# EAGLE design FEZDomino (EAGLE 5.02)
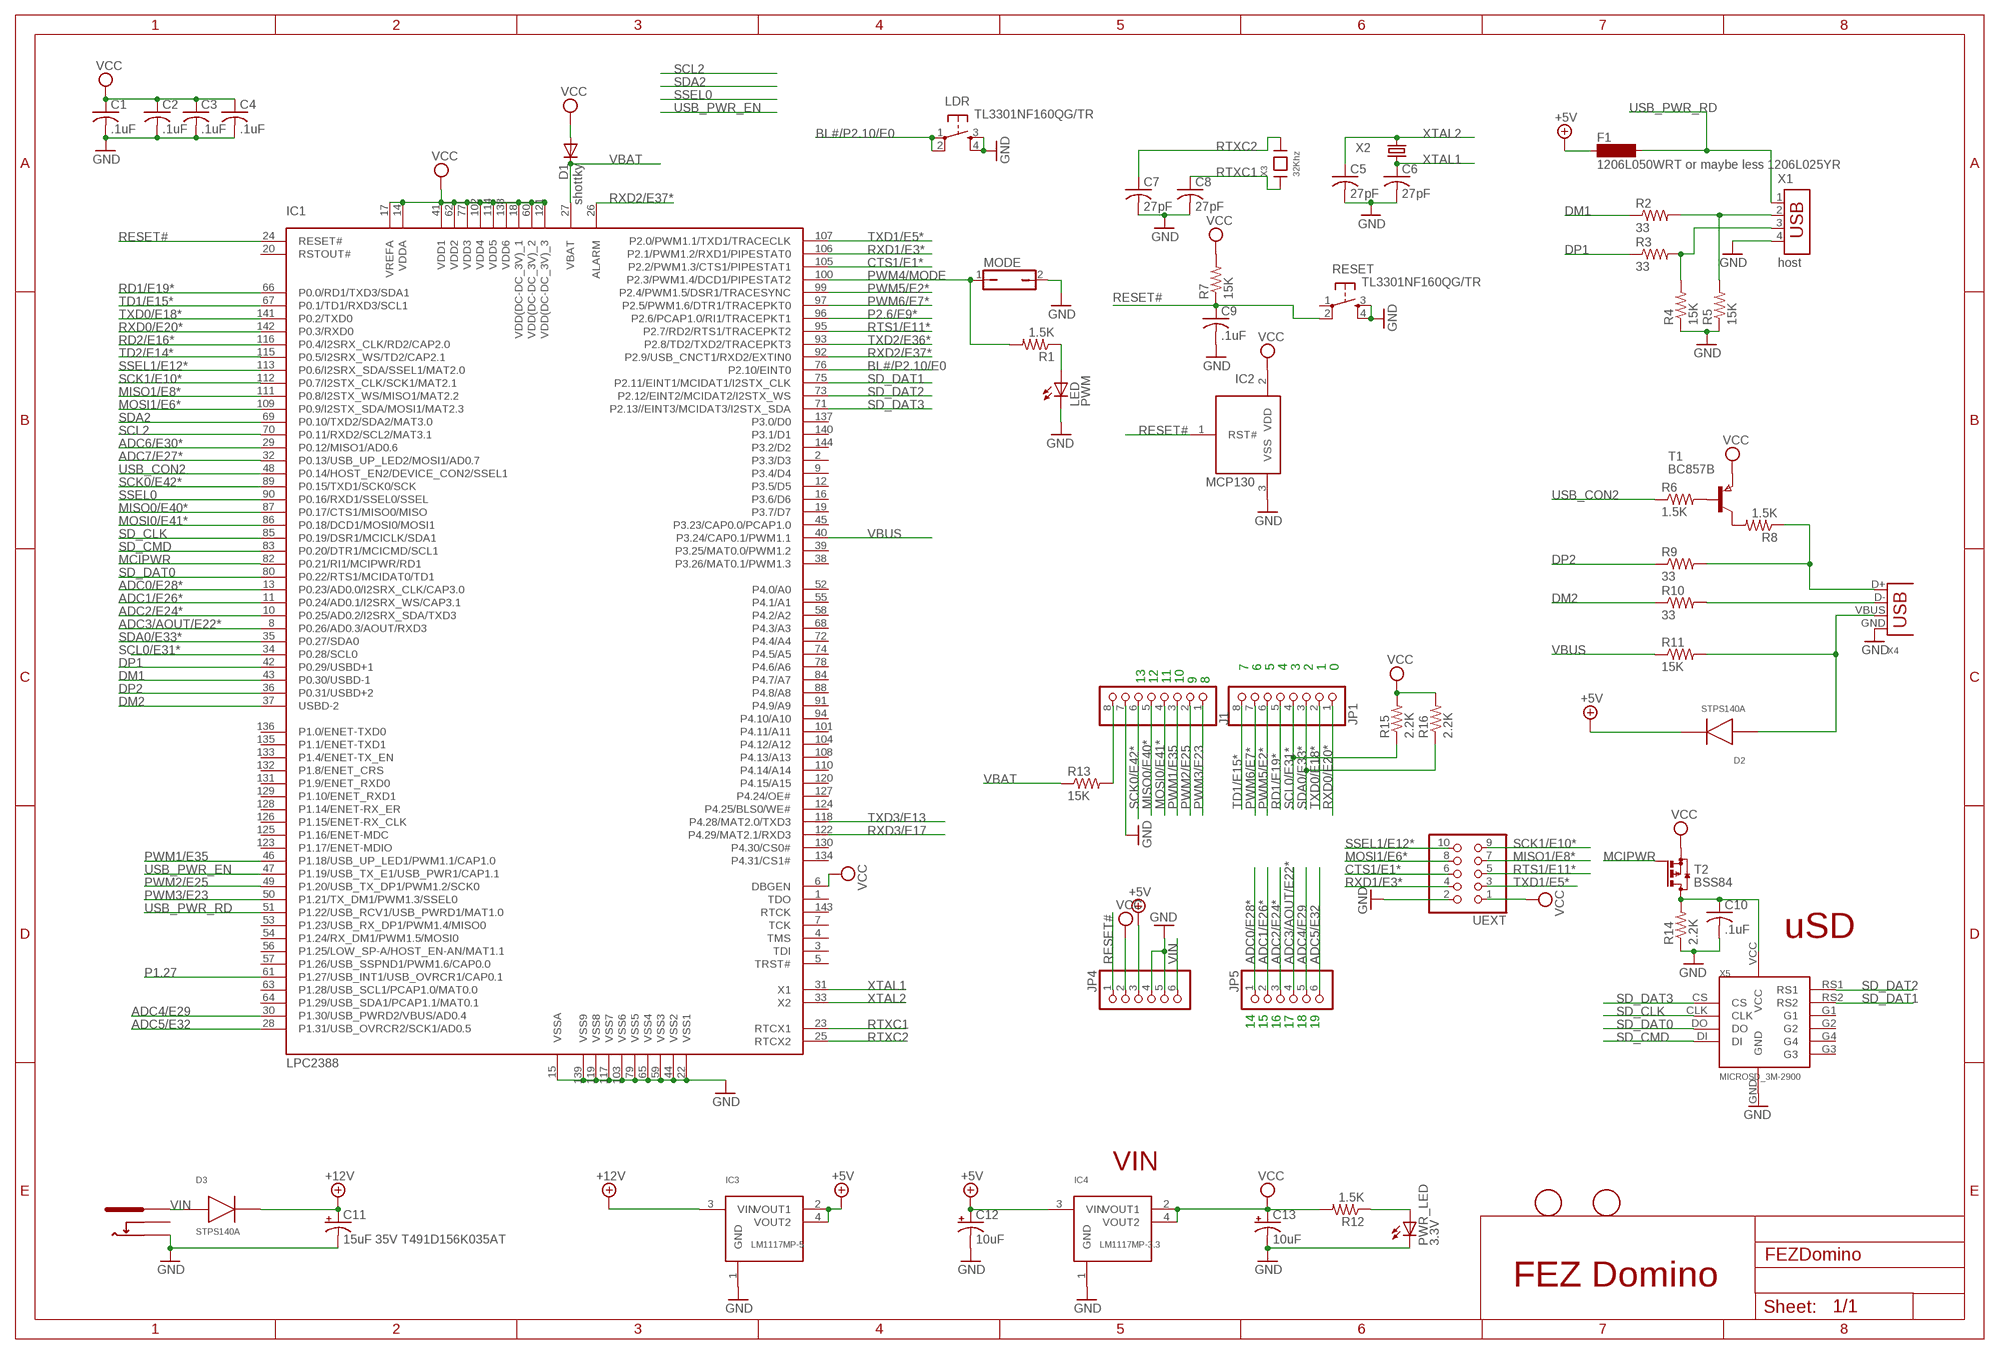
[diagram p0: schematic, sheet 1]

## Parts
C1  .1uF  C-USC0603K  [C0603K]
C2  .1uF  C-USC0603K  [C0603K]
C3  .1uF  C-USC0603K  [C0603K]
C4  .1uF  C-USC0603K  [C0603K]
C5  27pF  C-USC0603K  [C0603K]
C6  27pF  C-USC0603K  [C0603K]
C7  27pF  C-USC0603K  [C0603K]
C8  27pF  C-USC0603K  [C0603K]
C9  .1uF  C-USC0603K  [C0603K]
C10  .1uF  C-USC0603  [C0603]
C11  15uF 35V T491D156K035AT  CPOL-USD/7343-31W  [D/7343-31W]
C12  10uF  CPOL-USCT3528  [CT3528]
C13  10uF  CPOL-USCT3528  [CT3528]
D1  shottky  DIODE-SOD323-W  [SOD323-W]
D2  STPS140A  DIODE_SMA  [DIODE_SMA]
D3  STPS140A  DIODE_SMA  [DIODE_SMA]
F1  1206L050WRT or maybe less 1206L025YR  SM-1206  [SM-1206]
IC1  LPC2388  [LQFP144]
IC2  MCP130  [SOT23]
IC3  LM1117MP-5  LM1117  [SOT223]
IC4  LM1117MP-3.3  LM1117  [SOT223]
J1  PINHD-1X8  [1X08]
JP1  PINHD-1X8  [1X08]
JP4  PINHD-1X6  [1X06]
JP5  PINHD-1X6  [1X06]
LDR  TL3301NF160QG/TR  DTSM-6  [DTSM-6]
LED  PWM  LEDCHIPLED_0805  [CHIPLED_0805]
MODE  JP1Q  [JP1]
PWR_LED  3.3V  LEDCHIPLED_0805  [CHIPLED_0805]
R1  1.5K  R-US_R0603  [R0603]
R2  33  R-US_R0603  [R0603]
R3  33  R-US_R0603  [R0603]
R4  15K  R-US_R0603  [R0603]
R5  15K  R-US_R0603  [R0603]
R6  1.5K  R-US_R0603  [R0603]
R7  15K  R-US_R0603  [R0603]
R8  1.5K  R-US_R0603  [R0603]
R9  33  R-US_R0603  [R0603]
R10  33  R-US_R0603  [R0603]
R11  15K  R-US_R0603  [R0603]
R12  1.5K  R-US_R0603  [R0603]
R13  15K  R-US_R0603  [R0603]
R14  2.2K  R-US_R0603  [R0603]
R15  2.2K  R-US_R0603  [R0603]
R16  2.2K  R-US_R0603  [R0603]
RESET  TL3301NF160QG/TR  DTSM-6  [DTSM-6]
T1  BC857B  PNPSOT23  [SOT-23]
T2  BSS84  [SOT23]
U$1  FIDUCIALMOUNT  [FIDUCIA-MOUNT]
U$2  FIDUCIALMOUNT  [FIDUCIA-MOUNT]
UEXT  PINHD-2X5  [2X05]
X1  host  USB-787616  [USB]
X2  12Mhz  CRYTALSM49  [SM49]
X3  32Khz  CRYSTAL_6.9X1.4  [CRYSTAL_6.9X1.4]
X4  DX2R005HN2E700  USB-MB-S  [USB-MB-S]
X5  MICROSD_3M-2900  [USD_3M-2900]
X6  PJ-102B_POWER_CON  [PJ-102B_POWER_CON]

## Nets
+5V: C12.+ D2.K F1.1 IC3.2(VOUT1) IC3.4(VOUT2) IC4.3(VIN) JP4.3
+12V: C11.+ D3.K IC3.3(VIN)
ADC0/E28*: IC1.13(P0.23/AD0.0/I2SRX_CLK/CAP3.0) JP5.1
ADC1/E26*: IC1.11(P0.24/AD0.1/I2SRX_WS/CAP3.1) JP5.2
ADC2/E24*: IC1.10(P0.25/AD0.2/I2SRX_SDA/TXD3) JP5.3
ADC3/AOUT/E22*: IC1.8(P0.26/AD0.3/AOUT/RXD3) JP5.4
ADC4/E29: IC1.30(P1.30/USB_PWRD2/VBUS/AD0.4) JP5.5
ADC5/E32: IC1.28(P1.31/USB_OVRCR2/SCK1/AD0.5) JP5.6
ADC6/E30*: IC1.29(P0.12/MISO1/AD0.6)
ADC7/E27*: IC1.32(P0.13/USB_UP_LED2/MOSI1/AD0.7)
BL#/P2.10/E0: IC1.76(P2.10/EINT0) LDR.1 LDR.2
CTS1/E1*: IC1.105(P2.2/PWM1.3/CTS1/PIPESTAT1) UEXT.6
DM1: IC1.43(P0.30/USBD-1) R2.1
DM2: IC1.37(USBD-2) R10.1
DP1: IC1.42(P0.29/USBD+1) R3.1
DP2: IC1.36(P0.31/USBD+2) R9.1
GND: C1.2 C2.2 C3.2 C4.2 C5.2 C6.2 C7.2 C8.2 C9.2 C10.2 C11.- C12.- C13.- IC1.15(VSSA) IC1.22(VSS1) IC1.44(VSS2) IC1.59(VSS3) IC1.65(VSS4) IC1.79(VSS5) IC1.103(VSS6) IC1.117(VSS7) IC1.119(VSS8) IC1.139(VSS9) IC2.3(VSS) IC3.1(GND) IC4.1(GND) J1.7 JP4.4 JP4.5 LDR.3 LDR.4 LED.C MODE.2 PWR_LED.C R4.1 R5.1 R14.1 RESET.3 RESET.4 UEXT.2 X1.4 X4.GND X5.GND X6.OUT
MCIPWR: IC1.82(P0.21/RI1/MCIPWR/RD1) T2.1(G)
MISO0/E40*: IC1.87(P0.17/CTS1/MISO0/MISO) J1.5
MISO1/E8*: IC1.111(P0.8/I2STX_WS/MISO1/MAT2.2) UEXT.7
MOSI0/E41*: IC1.86(P0.18/DCD1/MOSI0/MOSI1) J1.4
MOSI1/E6*: IC1.109(P0.9/I2STX_SDA/MOSI1/MAT2.3) UEXT.8
N$1: R6.2 T1.3(B)
N$2: PWR_LED.A R12.1
N$3: LED.A R1.1
N$4: R8.2 T1.1(C)
N$5: J1.8 R13.2
N$9: D2.A R11.2 X4.VBUS
N$146: R2.2 R5.2 X1.2
N$152: R3.2 R4.2 X1.3
N$153: R8.1 R9.2 X4.D+
N$155: R10.2 X4.D-
P1.27: IC1.61(P1.27/USB_INT1/USB_OVRCR1/CAP0.1)
P2.6/E9*: IC1.96(P2.6/PCAP1.0/RI1/TRACEPKT1)
PWM1/E35: IC1.46(P1.18/USB_UP_LED1/PWM1.1/CAP1.0) J1.3
PWM2/E25: IC1.49(P1.20/USB_TX_DP1/PWM1.2/SCK0) J1.2
PWM3/E23: IC1.50(P1.21/TX_DM1/PWM1.3/SSEL0) J1.1
PWM4/MODE: IC1.100(P2.3/PWM1.4/DCD1/PIPESTAT2) MODE.1 R1.2
PWM5/E2*: IC1.99(P2.4/PWM1.5/DSR1/TRACESYNC) JP1.6
PWM6/E7*: IC1.97(P2.5/PWM1.6/DTR1/TRACEPKT0) JP1.7
RD1/E19*: IC1.66(P0.0/RD1/TXD3/SDA1) JP1.5
RD2/E16*: IC1.116(P0.4/I2SRX_CLK/RD2/CAP2.0)
RESET#: C9.1 IC1.24(RESET#) IC2.1(RST#) JP4.1 R7.1 RESET.2
RTS1/E11*: IC1.95(P2.7/RD2/RTS1/TRACEPKT2) UEXT.5
RTXC1: C8.1 IC1.23(RTCX1) X3.1
RTXC2: C7.1 IC1.25(RTCX2) X3.4
RXD0/E20*: IC1.142(P0.3/RXD0) JP1.1
RXD1/E3*: IC1.106(P2.1/PWM1.2/RXD1/PIPESTAT0) UEXT.4
RXD2/E37*: IC1.26(ALARM) IC1.92(P2.9/USB_CNCT1/RXD2/EXTIN0)
RXD3/E17: IC1.122(P4.29/MAT2.1/RXD3)
SCK0/E42*: IC1.89(P0.15/TXD1/SCK0/SCK) J1.6
SCK1/E10*: IC1.112(P0.7/I2STX_CLK/SCK1/MAT2.1) UEXT.9
SCL0/E31*: IC1.34(P0.28/SCL0) JP1.4 R15.1
SCL2: IC1.70(P0.11/RXD2/SCL2/MAT3.1)
SD_CLK: IC1.85(P0.19/DSR1/MCICLK/SDA1) X5.CLK
SD_CMD: IC1.83(P0.20/DTR1/MCICMD/SCL1) X5.DI
SD_DAT0: IC1.80(P0.22/RTS1/MCIDAT0/TD1) X5.DO
SD_DAT1: IC1.75(P2.11/EINT1/MCIDAT1/I2STX_CLK) X5.RS2
SD_DAT2: IC1.73(P2.12/EINT2/MCIDAT2/I2STX_WS) X5.RS1
SD_DAT3: IC1.71(P2.13//EINT3/MCIDAT3/I2STX_SDA) X5.CS
SD_PWR: C10.1 R14.2 T2.3(D) X5.VCC
SDA0/E33*: IC1.35(P0.27/SDA0) JP1.3 R16.1
SDA2: IC1.69(P0.10/TXD2/SDA2/MAT3.0)
SSEL0: IC1.90(P0.16/RXD1/SSEL0/SSEL)
SSEL1/E12*: IC1.113(P0.6/I2SRX_SDA/SSEL1/MAT2.0) UEXT.10
TD1/E15*: IC1.67(P0.1/TD1/RXD3/SCL1) JP1.8
TD2/E14*: IC1.115(P0.5/I2SRX_WS/TD2/CAP2.1)
TXD0/E18*: IC1.141(P0.2/TXD0) JP1.2
TXD1/E5*: IC1.107(P2.0/PWM1.1/TXD1/TRACECLK) UEXT.3
TXD2/E36*: IC1.93(P2.8/TD2/TXD2/TRACEPKT3)
TXD3/E13: IC1.118(P4.28/MAT2.0/TXD3)
USB_CON2: IC1.48(P0.14/HOST_EN2/DEVICE_CON2/SSEL1) R6.1
USB_PWR_EN: IC1.47(P1.19/USB_TX_E1/USB_PWR1/CAP1.1)
USB_PWR_RD: F1.2 IC1.51(P1.22/USB_RCV1/USB_PWRD1/MAT1.0) X1.1
VBAT: D1.C IC1.27(VBAT) R13.1
VBUS: IC1.40(P3.24/CAP0.1/PWM1.1) R11.1
VCC: C1.1 C2.1 C3.1 C4.1 C13.+ D1.A IC1.6(DBGEN) IC1.14(VDDA) IC1.17(VREFA) IC1.18(VDD(DC-DC_3V)_1) IC1.41(VDD1) IC1.60(VDD(DC-DC_3V)_2) IC1.62(VDD2) IC1.77(VDD3) IC1.102(VDD4) IC1.114(VDD5) IC1.121(VDD(DC-DC_3V)_3) IC1.138(VDD6) IC2.2(VDD) IC4.2(VOUT1) IC4.4(VOUT2) JP4.2 R7.2 R12.2 R15.2 R16.2 T1.2(E) T2.2(S) UEXT.1
VIN: D3.A JP4.6 X6.IN
XTAL1: C6.1 IC1.31(X1) X2.1
XTAL2: C5.1 IC1.33(X2) X2.2
Unconnected: IC1.1(TDO) IC1.2(P3.3/D3) IC1.3(TDI) IC1.4(TMS) IC1.5(TRST#) IC1.7(TCK) IC1.9(P3.4/D4) IC1.12(P3.5/D5) IC1.16(P3.6/D6) IC1.19(P3.7/D7) IC1.20(RSTOUT#) IC1.21(NC1) IC1.38(P3.26/MAT0.1/PWM1.3) IC1.39(P3.25/MAT0.0/PWM1.2) IC1.45(P3.23/CAP0.0/PCAP1.0) IC1.52(P4.0/A0) IC1.53(P1.23/USB_RX_DP1/PWM1.4/MISO0) IC1.54(P1.24/RX_DM1/PWM1.5/MOSI0) IC1.55(P4.1/A1) IC1.56(P1.25/LOW_SP-A/HOST_EN-AN/MAT1.1) IC1.57(P1.26/USB_SSPND1/PWM1.6/CAP0.0) IC1.58(P4.2/A2) IC1.63(P1.28/USB_SCL1/PCAP1.0/MAT0.0) IC1.64(P1.29/USB_SDA1/PCAP1.1/MAT0.1) IC1.68(P4.3/A3) IC1.72(P4.4/A4) IC1.74(P4.5/A5) IC1.78(P4.6/A6) IC1.81(NC2) IC1.84(P4.7/A7) IC1.88(P4.8/A8) IC1.91(P4.9/A9) IC1.94(P4.10/A10) IC1.98(NC3) IC1.101(P4.11/A11) IC1.104(P4.12/A12) IC1.108(P4.13/A13) IC1.110(P4.14/A14) IC1.120(P4.15/A15) IC1.123(P1.17/ENET-MDIO) IC1.124(P4.25/BLS0/WE#) IC1.125(P1.16/ENET-MDC) IC1.126(P1.15/ENET-RX_CLK) IC1.127(P4.24/OE#) IC1.128(P1.14/ENET-RX_ER) IC1.129(P1.10/ENET_RXD1) IC1.130(P4.30/CS0#) IC1.131(P1.9/ENET_RXD0) IC1.132(P1.8/ENET_CRS) IC1.133(P1.4/ENET-TX_EN) IC1.134(P4.31/CS1#) IC1.135(P1.1/ENET-TXD1) IC1.136(P1.0/ENET-TXD0) IC1.137(P3.0/D0) IC1.140(P3.1/D1) IC1.143(RTCK) IC1.144(P3.2/D2) RESET.1 X5.G1 X5.G2 X5.G3 X5.G4 X6.OUT_CON

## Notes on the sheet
- 7 | 6 | 5 | 4 | 3 | 2 | 1 | 0
- 13 | 12 | 11 | 10 | 9 | 8
- uSD
- 14 | 15 | 16 | 17 | 18 | 19
- VIN
- FEZ Domino

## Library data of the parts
C1-C10 = rcl:C-US: CAPACITOR, American symbol
C11-C13 = rcl:CPOL-US: POLARIZED CAPACITOR, American symbol
D1 = diode:DIODE-: DIODE
D2 D3 = GHI:DIODE_SMA
F1 = inductor-neosid:SM-1206: INDUCTOR
IC1 = GHI:LPC2388
IC2 = GHI:MCP130
IC3 IC4 = GHI:LM1117
J1 JP1 = pinhead:PINHD-1X8: PIN HEADER
JP4 JP5 = pinhead:PINHD-1X6: PIN HEADER
LDR RESET = switch-tact:DTSM-6
LED PWR_LED = led:LED: LED
MODE = jumper:JP1Q: JUMPER
R1-R16 = rcl:R-US_: RESISTOR, American symbol
T1 = zetex:PNPSOT23: PNP TRANSISTOR
T2 = transistor-small-signal:BSS84: P-CHANNEL MOS FET
U$1 U$2 = SmartPrj:FIDUCIALMOUNT
UEXT = pinhead:PINHD-2X5: PIN HEADER
X1 = con-amp:USB-787616: AMP connector
X2 = crystal:CRYTAL: CRYSTAL
X3 = GHI:CRYSTAL_6.9X1.4
X4 = con-usb-3:USB: USB Connectors
X5 = GHI:MICROSD_3M-2900
X6 = GHI:PJ-102B_POWER_CON

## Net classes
0 default: width 0.254 mm, drill 0.381 mm, clearance 0.203 mm
2 gnd: width 0.254 mm, drill 0.381 mm, clearance 0.203 mm
3 usbvcc: width 0.508 mm, drill 0.508 mm, clearance 2.235 mm

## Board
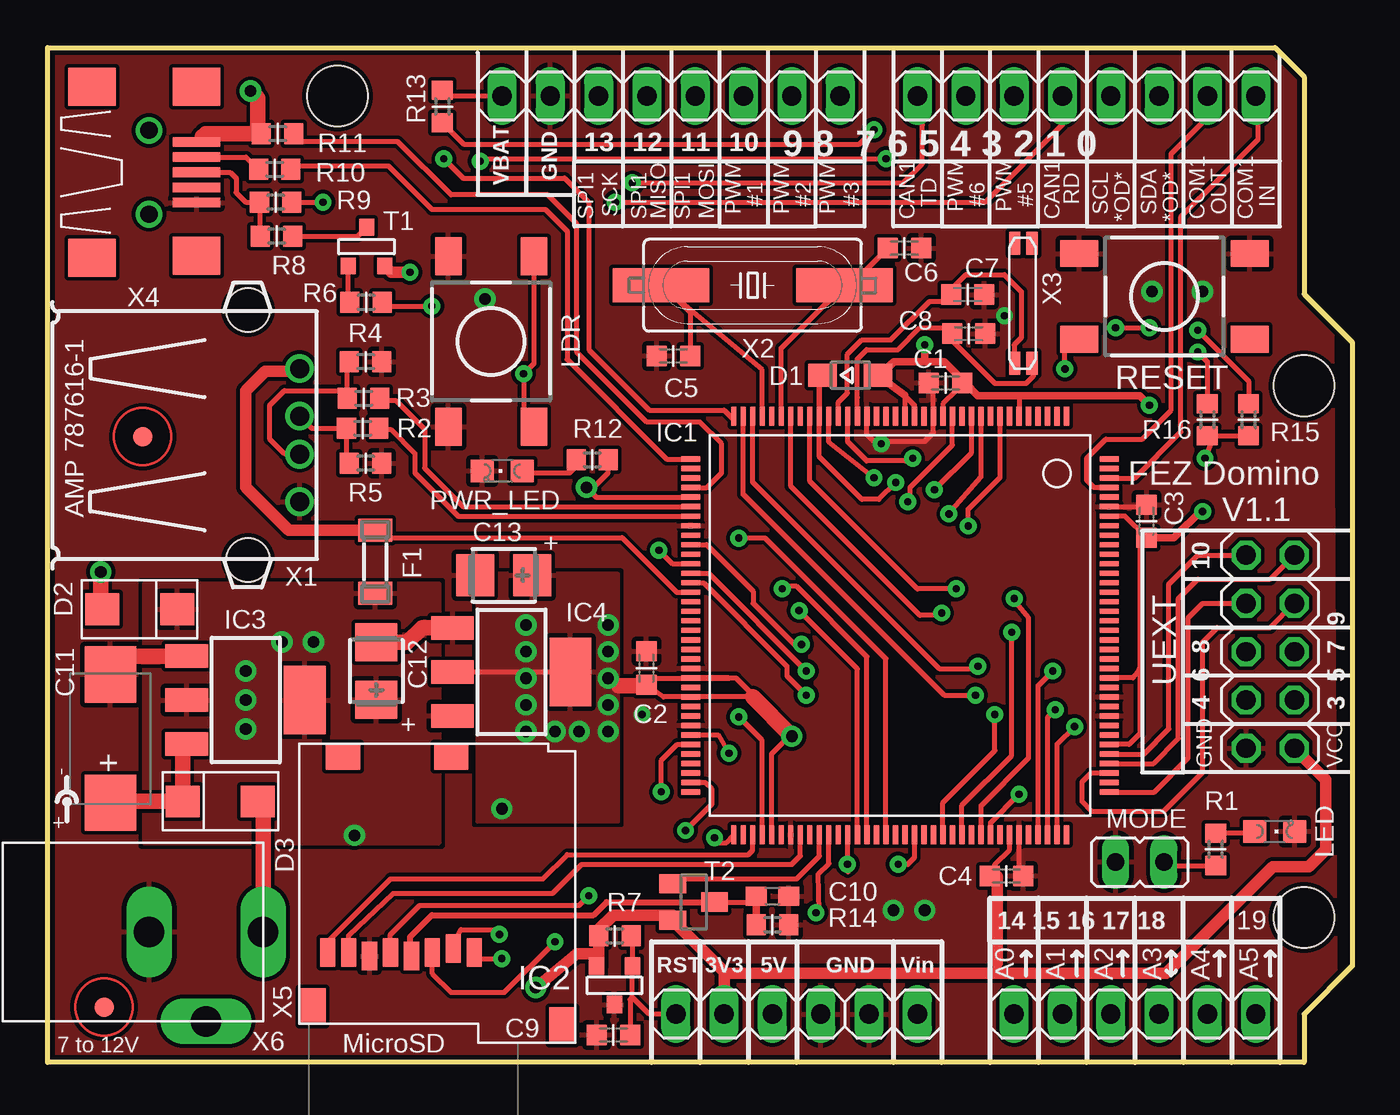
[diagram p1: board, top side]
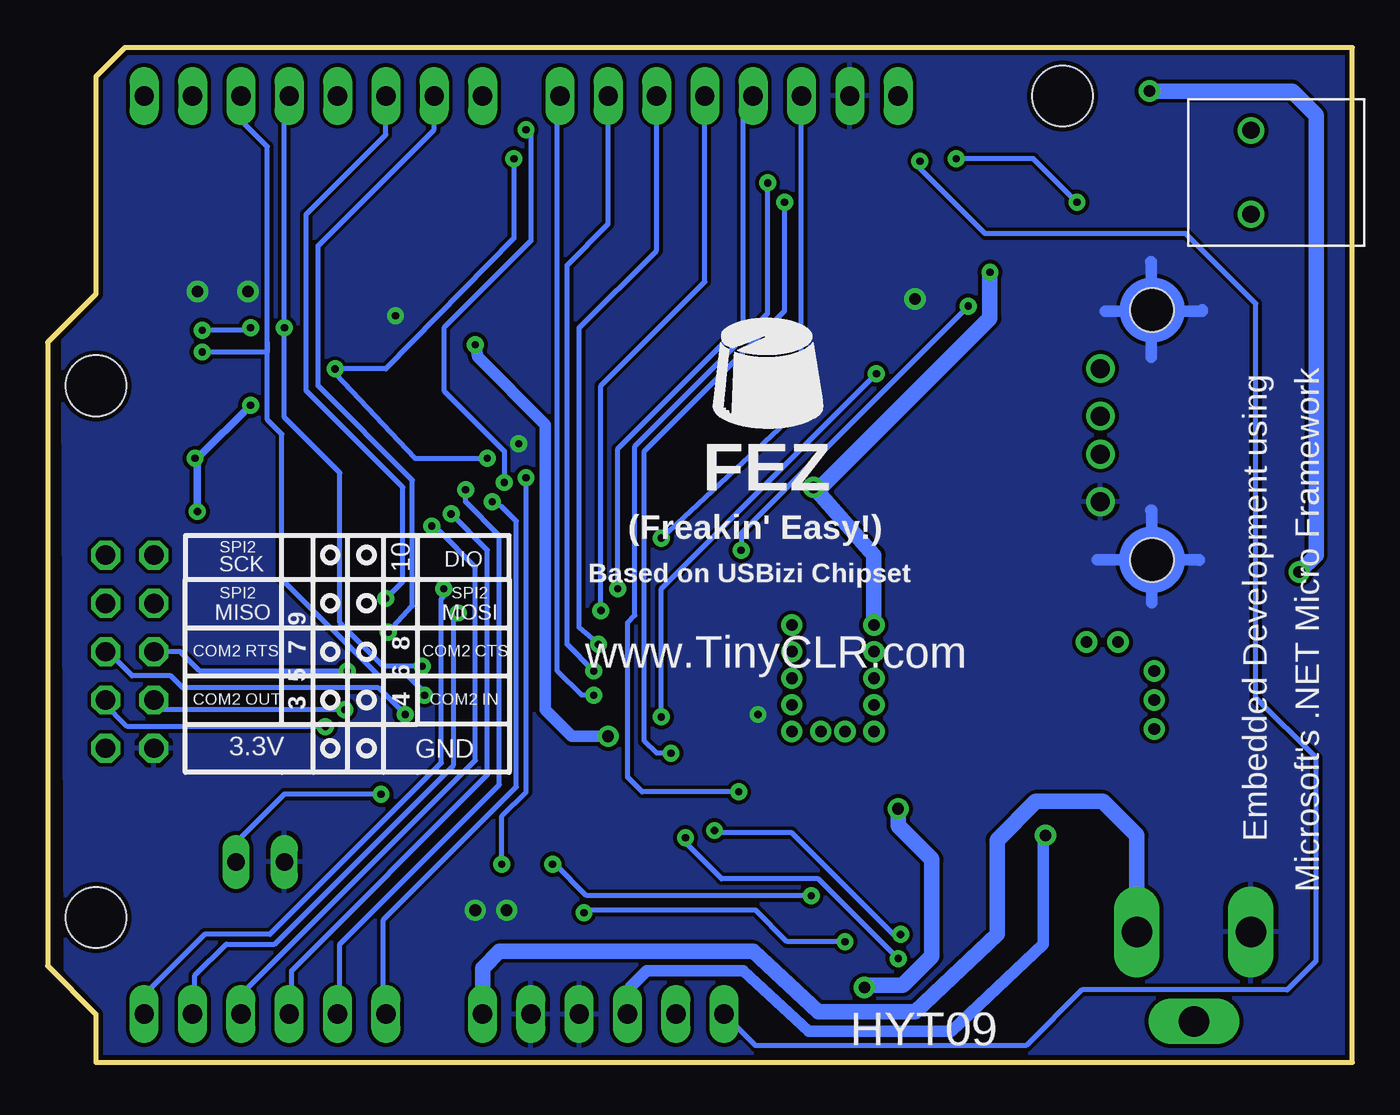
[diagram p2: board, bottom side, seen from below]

Size 68.58 x 53.34 mm. Coordinates in mm from the lower left corner, seen from the top.
Outline: 0,53.34 64.52,53.34 66.04,51.82 66.04,40.39 68.58,37.85 68.58,5.08 66.04,2.54 66.04,0 0,0 0,53.34
Copper layers (1+16): Top 0.035mm / dielectric 1.5mm / Bottom 0.035mm
Design rules "default *": minimum track width 6mil, minimum drill 12mil, track to track 6mil, track to pad 6mil, pad to pad 6mil, via to via 6mil, smd to smd 6mil, copper to edge 10mil, drill to drill 6mil, minimum pad ring 10mil, minimum via ring 10mil, stop-mask expansion 16mil, vias tented up to drill 25mil, thermal gap 10mil
Holes 3.2 mm at 66.04,35.56 66.04,7.62 15.24,50.8

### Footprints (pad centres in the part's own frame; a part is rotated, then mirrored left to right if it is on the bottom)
C0603K = smd 1.05 x 1.08: 1 -0.875,0; 2 0.875,0
C0603 = smd 1.1 x 1: 1 -0.85,0; 2 0.85,0
D/7343-31W = smd 2.95 x 2.7: + 3.375,0; - -3.375,0
CT3528 = smd 2 x 2.2: + 1.5,0; - -1.5,0
SOD323-W = smd 1.5 x 1.2: A 1.45,0; C -1.45,0
DIODE_SMA = smd 1.778 x 1.676: A -1.905,0; K 2.032,0
SM-1206 = smd 1.2 x 1.8: 1 -1.65,0; 2 1.65,0
LQFP144 = smd 0.28 x 1: 1 -8.5,-11; 2 -8,-11; 3 -7.5,-11; 4 -7,-11; 5 -6.5,-11; 6 -6,-11; 7 -5.5,-11; 8 -5,-11; 9 -4.5,-11; 10 -4,-11; 11 -3.5,-11; 12 -3,-11; 13 -2.5,-11; 14 -2,-11; 15 -1.5,-11; 16 -1,-11; 17 -0.5,-11; 18 0,-11; 19 0.5,-11; 20 1,-11; 21 1.5,-11; 22 2,-11; 23 2.5,-11; 24 3,-11; 25 3.5,-11; 26 4,-11; 27 4.5,-11; 28 5,-11; 29 5.5,-11; 30 6,-11; 31 6.5,-11; 32 7,-11; 33 7.5,-11; 34 8,-11; 35 8.5,-11; 36 9,-11; 73 9,11; 74 8.5,11; 75 8,11; 76 7.5,11; 77 7,11; 78 6.5,11; 79 6,11; 80 5.5,11; 81 5,11; 82 4.5,11; 83 4,11; 84 3.5,11; 85 3,11; 86 2.5,11; 87 2,11; 88 1.5,11; 89 1,11; 90 0.5,11; 91 0,11; 92 -0.5,11; 93 -1,11; 94 -1.5,11; 95 -2,11; 96 -2.5,11; 97 -3,11; 98 -3.5,11; 99 -4,11; 100 -4.5,11; 101 -5,11; 102 -5.5,11; 103 -6,11; 104 -6.5,11; 105 -7,11; 106 -7.5,11; 107 -8,11; 108 -8.5,11 | smd 1 x 0.28: 37 11.25,-8.75; 38 11.25,-8.25; 39 11.25,-7.75; 40 11.25,-7.25; 41 11.25,-6.75; 42 11.25,-6.25; 43 11.25,-5.75; 44 11.25,-5.25; 45 11.25,-4.75; 46 11.25,-4.25; 47 11.25,-3.75; 48 11.25,-3.25; 49 11.25,-2.75; 50 11.25,-2.25; 51 11.25,-1.75; 52 11.25,-1.25; 53 11.25,-0.75; 54 11.25,-0.25; 55 11.25,0.25; 56 11.25,0.75; 57 11.25,1.25; 58 11.25,1.75; 59 11.25,2.25; 60 11.25,2.75; 61 11.25,3.25; 62 11.25,3.75; 63 11.25,4.25; 64 11.25,4.75; 65 11.25,5.25; 66 11.25,5.75; 67 11.25,6.25; 68 11.25,6.75; 69 11.25,7.25; 70 11.25,7.75; 71 11.25,8.25; 72 11.25,8.75; 109 -10.75,8.75; 110 -10.75,8.25; 111 -10.75,7.75; 112 -10.75,7.25; 113 -10.75,6.75; 114 -10.75,6.25; 115 -10.75,5.75; 116 -10.75,5.25; 117 -10.75,4.75; 118 -10.75,4.25; 119 -10.75,3.75; 120 -10.75,3.25; 121 -10.75,2.75; 122 -10.75,2.25; 123 -10.75,1.75; 124 -10.75,1.25; 125 -10.75,0.75; 126 -10.75,0.25; 127 -10.75,-0.25; 128 -10.75,-0.75; 129 -10.75,-1.25; 130 -10.75,-1.75; 131 -10.75,-2.25; 132 -10.75,-2.75; 133 -10.75,-3.25; 134 -10.75,-3.75; 135 -10.75,-4.25; 136 -10.75,-4.75; 137 -10.75,-5.25; 138 -10.75,-5.75; 139 -10.75,-6.25; 140 -10.75,-6.75; 141 -10.75,-7.25; 142 -10.75,-7.75; 143 -10.75,-8.25; 144 -10.75,-8.75
SOT23 = smd 0.813 x 0.914: 1 -0.95,-0.973; 2 0.95,-0.973; 3 0,1.049
SOT223 = smd 1.219 x 2.235: 1 -2.311,-3.099; 2 0,-3.099; 3 2.311,-3.099 | smd 3.6 x 2.2: 4 0,3.099
1X08 = drill 1.016 long: 1 -8.89,0; 2 -6.35,0; 3 -3.81,0; 4 -1.27,0; 5 1.27,0; 6 3.81,0; 7 6.35,0; 8 8.89,0
1X06 = drill 1.016 long: 1 -6.35,0; 2 -3.81,0; 3 -1.27,0; 4 1.27,0; 5 3.81,0; 6 6.35,0
DTSM-6 = smd 2 x 1.4: 1 -4.475,2.25; 2 4.475,2.25; 3 -4.475,-2.25; 4 4.475,-2.25
CHIPLED_0805 = smd 1.2 x 1.2: A 0,-1.05; C 0,1.05
JP1 = drill 0.914 long: 1 0,-1.27; 2 0,1.27
R0603 = smd 1 x 1.1: 1 -0.85,0; 2 0.85,0
SOT-23 = smd 0.787 x 0.889: 1 0.025,-1.016; 2 -0.94,1.016; 3 0.991,1.016
SOT23' = smd 1 x 1.4: 1 -0.95,-1.1; 2 0.95,-1.1; 3 0,1.1
FIDUCIA-MOUNT = smd 1.016 x 1.016: P$1 0,0
2X05 = drill 1.016 octagon: 1 -5.08,-1.27; 2 -5.08,1.27; 3 -2.54,-1.27; 4 -2.54,1.27; 5 0,-1.27; 6 0,1.27; 7 2.54,-1.27; 8 2.54,1.27; 9 5.08,-1.27; 10 5.08,1.27
USB = drill 1 round: 1 -3.5,12.99; 2 -1,12.99; 3 1,12.99; 4 3.5,12.99 | hole 2.3: -6.57,10.28; 6.57,10.28
SM49@1 = smd 5.08 x 1.778: 1 -4.826,0; 2 4.826,0
CRYSTAL_6.9X1.4 = smd 1.2 x 0.6: 1 -3.1,-0.4; 2 3.2,-0.4; 3 3.2,0.5; 4 -3.1,0.5
USB-MB-S = smd 2.5 x 0.5: D+ 2.5,0; D- 2.5,0.8; GND 2.5,-1.6; ID 2.5,-0.8; VBUS 2.5,1.6 | smd 2.5 x 2: P$1 -3,-4.5; P$2 -3,4.5; P$3 2.5,-4.4; P$4 2.5,4.5 | drill 0.9 round: P$5 0,2.2; P$6 0,-2.2
USD_3M-2900 = smd 0.8 x 1.5: CLK 1.18,3.1; CS -2.12,2.9; DI -1.02,3.1; DO 3.38,3.1; GND 2.28,3.3; RS1 -3.22,3.1; RS2 4.48,3.1; VCC 0.08,3.3 | smd 1.4 x 1.9: G1 -7.87,6.95; G4 5.28,5.95 | smd 1.8 x 1.4: G2 -2.02,-7.2; G3 3.68,-7.2
PJ-102B_POWER_CON = drill 1.6 long: IN -6,0; OUT 0,0; OUT_CON -3,4.7

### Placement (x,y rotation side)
C1  47.19,35.71 180 top
C2  31.47,20.73 90 top
C3  57.76,28.45 90 top
C4  50.39,9.8 0 top
C5  32.89,37.13 180 top
C6  45.03,42.8 0 top
C7  48.36,40.36 0 top
C8  48.41,38.3 0 top
C9  29.74,1.45 180 top
C10  38.1,8.74 0 top
C11  3.3,17.02 270 top
C12  17.27,20.57 270 top
C13  23.98,25.6 0 top
D1  42.19,36.12 0 top
D2  4.78,23.83 0 top
D3  9.14,13.72 180 top
F1  17.22,26.31 90 top
IC1  45.06,22.96 180 top
IC2  29.79,4.09 180 top
IC3  10.41,19.05 270 top
IC4  24.38,20.52 270 top
J1  32.77,50.8 180 top
JP1  54.61,50.8 180 top
JP4  39.37,2.54 0 top
JP5  57.15,2.54 0 top
LDR  23.32,37.9 270 top
LED  64.49,12.14 270 top
MODE  57.4,10.54 90 top
PWR_LED  23.9,31.09 90 top
R1  61.39,11.2 270 top
R2  16.56,33.32 180 top
R3  16.61,34.9 180 top
R4  16.71,36.83 180 top
R5  16.71,31.5 180 top
R6  16.74,39.95 180 top
R7  29.82,6.65 180 top
R8  12.04,43.43 0 top
R9  11.99,45.21 180 top
R10  11.94,46.94 180 top
R11  12.09,48.82 180 top
R12  28.63,31.67 0 top
R13  20.75,50.24 90 top
R14  38.1,7.24 180 top
R15  63.12,33.78 270 top
R16  60.96,33.78 270 top
RESET  58.7,40.26 180 top
T1  16.79,42.88 180 top
T2  BSS84  [SOT23']  33.96,8.43 270 top
U$1  2.97,2.9 0 top
U$2  5,32.89 0 top
UEXT  64.26,21.59 90 top
X1  0.25,32.97 270 top
X2  12Mhz  [SM49@1]  37.06,40.84 180 top
X3  51.33,39.85 90 top
X4  5.33,46.79 0 top
X5  19.2,8.89 180 top
X6  5.33,6.86 180 top

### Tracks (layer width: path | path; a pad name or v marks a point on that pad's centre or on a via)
+5V  (via drill 0.61)
  Bottom 0.254: 16.26,11.81 v16.13,11.94
  Bottom 0.61: JP4.3 37.97,3.94 37.08,4.83 32,4.83 28.57,1.65 21.08,1.65 16.26,6.22 16.26,11.81
  other vias: 10.41,20.57 10.41,17.53 10.41,19.05 12.32,22.1 13.97,22.1
  pour Top: 20.57,11.56 20.57,25.15 5.08,25.15 5.08,11.56
+12V
  Top 0.254: 7.11,16.54 IC3.3 | C11.+ 3.38,13.72
  Top 0.813: 7.11,16.54 D3.K 3.38,13.72
ADC0/E28*  (via drill 0.38)
  Top 0.254: IC1.13 47.56,32.45 45.34,30.23 45.34,29.59 v45.21,29.46
  Bottom 0.254: v45.21,29.46 44.7,29.21 43.94,28.45 43.94,14.48 50.93,7.49 50.93,2.67 JP5.1
ADC1/E26*  (via drill 0.38)
  Top 0.254: IC1.11 48.56,32.05 v46.61,30.1
  Bottom 0.254: v46.61,30.1 46.61,29.46 44.83,27.69 44.83,14.61 53.21,6.22 53.21,2.67 JP5.2
ADC2/E24*  (via drill 0.38)
  Top 0.254: IC1.10 49.06,30.77 v47.37,28.83
  Bottom 0.254: v47.37,28.83 45.47,26.92 45.47,15.11 55.75,4.83 55.75,2.67 JP5.3
ADC3/AOUT/E22*  (via drill 0.38)
  Top 0.254: IC1.8 50.06,30.76 48.39,29.08 v48.39,28.19
  Bottom 0.254: JP5.4 58.42,3.56 46.1,15.88 46.1,26.04 48.01,27.94 v48.39,28.19
ADC4/E29  (via drill 0.38)
  Top 0.254: IC1.30 39.06,30.28 45.85,23.5 46.86,23.5 v46.99,23.62
  Bottom 0.254: JP5.5 60.96,3.56 60.83,3.68 60.83,4.57 59.18,6.22 56.64,6.22 47.24,15.62 47.24,23.24 46.99,23.5 v46.99,23.62
ADC5/E32  (via drill 0.38)
  Top 0.254: 47.75,25.15 v47.75,24.89 45.72,24.89 40.06,30.55 IC1.28
  Bottom 0.254: JP5.6 63.5,3.56 60.33,6.73 56.9,6.73 47.88,15.75 47.88,24.38 47.75,24.51 v47.75,24.89
BL#/P2.10/E0  (via drill 0.38)
  Top 0.254: IC1.76 37.56,16.92 v36.32,18.16 | LDR.2 25.02,33.97 v25.02,36.2 25.57,36.74 LDR.1
  Bottom 0.254: v36.32,18.16 36.32,24.89 v25.02,36.2
CTS1/E1*  (via drill 0.38)
  Top 0.254: IC1.105 52.06,19.8 v52.83,20.57
  Bottom 0.254: v52.83,20.57 60.58,20.57 61.59,21.59 UEXT.6
DM1
  Top 0.254: IC1.43 21.58,28.71 19.3,30.99 19.3,32 18.03,33.27 17.46,33.27 R2.1
DM2
  Top 0.254: IC1.37 32.55,31.71 27.3,36.96 27.3,43.69 26.16,44.83 20.19,44.83 17.91,47.12 12.97,47.12 R10.1
DP1
  Top 0.254: IC1.42 21.84,29.21 19.81,31.24 19.81,33.27 18.29,34.8 17.56,34.8 R3.1
DP2  (via drill 0.38)
  Top 0.254: IC1.36 36.06,33.79 35.56,34.29 31.62,34.29 28.45,37.47 28.45,45.21 27.18,46.48 21.84,46.48 v20.83,47.5 | R9.1 v14.48,45.21
  Bottom 0.254: v20.83,47.5 16.76,47.5 v14.48,45.21
GND  (via drill 0.38, 0.61)
  Top 0.254: C1.2 46.56,35.47 IC1.15 46.56,33.1 46.1,32.64 43.43,32.64 43.06,33.01 IC1.22 | IC1.103 51.06,10.27 C4.2 | IC1.139 57.65,29.21 C3.2 | C11.- 4.27,21.36 | 21.26,22.86 IC4.1
  Top 0.813: 4.27,21.36 IC3.1 | C12.- 18.9,22.07 19.68,22.86 21.26,22.86
  Bottom 0.254: X1.4 13.21,29.47 13.21,29.46 13.21,29.49
  Bottom 0.61: 10.54,24.16 10.54,29.03 10.59,29.03 | 8.05,26.39 8.05,26.42 13.41,26.42 | 13.21,29.49 13.41,29.49 | 7.9,39.55 7.9,39.47 12.98,39.47 | 10.57,37.06 10.57,42.09 10.59,42.09
  other vias: 31.24,18.29 50.29,39.24 43.81,32.51 44.45,8 46.1,8 22.99,40.13 60.71,40.51 58.04,40.51
  pour Top (rank 6): 0.25,52.96 0.51,0 67.69,0 67.44,52.96
  pour Bottom (rank 2): 0.13,53.09 -0.13,0.13 67.56,0.13 67.82,53.09
MCIPWR
  Top 0.254: IC1.82 40.56,10.84 39.37,9.65 33.26,9.65 T2.1
MISO0/E40*  (via drill 0.38)
  Top 0.254: IC1.87 43.06,21.33 39.37,25.02 38.48,25.02 v38.61,24.89
  Bottom 0.254: J1.5 32,49.78 32,38.86 38.61,32.26 v38.61,24.89
MISO1/E8*
  Top 0.254: IC1.111 54.84,15.21 54.36,14.73 54.36,13.72 54.86,13.21 58.67,13.21 60.71,15.24 60.71,22.1 61.47,22.86 64.26,22.86 UEXT.7
MOSI0/E41*  (via drill 0.38)
  Top 0.254: IC1.86 42.56,20.69 v39.5,23.75
  Bottom 0.254: J1.4 34.04,41.02 39.5,35.56 v39.5,23.75
MOSI1/E6*
  Top 0.254: IC1.109 58.15,14.21 59.94,16 59.94,23.37 60.71,24.13 UEXT.8
N$1
  Top 0.254: T1.3 15.8,40.04 R6.2
N$2
  Top 0.254: R12.1 27.78,31.33 27.43,30.99 25.05,30.99 PWR_LED.A
N$3
  Top 0.254: R1.1 63.02,12.05 LED.A
N$4
  Top 0.254: R8.2 16.31,43.43 T1.1
N$5
  Top 0.254: J1.8 21.04,50.8 R13.2
N$9  (via drill 0.61)
  Top 0.254: R11.2 10.81,48.87 11.05,48.87 11.12,49.07 | D2.A 2.79,23.9
  Top 0.305: 8.13,48.64 8.13,48.51
  Top 0.406: X4.VBUS 7.96,48.51 8.13,48.51
  Top 0.813: 11.05,48.87 11.05,50.67 v10.67,51.05 | 2.79,23.9 v2.79,25.78 | 8.13,48.64 8.31,48.82 R11.2
  Bottom 0.813: v10.67,51.05 3.17,51.05 1.91,49.78 1.91,26.67 v2.79,25.78
N$146
  Top 0.254: X1.2 13.89,33.33 R2.2 15.71,31.65 R5.2
N$152
  Top 0.254: X1.3 13.21,32 12.45,32 11.68,32.77 11.68,34.54 12.45,35.31 15.49,35.31 15.76,35.04 R3.2 15.76,36.73 R4.2
N$153
  Top 0.254: X4.D+ 9.6,46.79 9.91,46.48 9.91,45.72 10.41,45.21 R9.2 11.14,43.48 R8.1
N$155
  Top 0.254: X4.D- 10.44,47.59 R10.2
PWM1/E35  (via drill 0.38)
  Top 0.254: IC1.46 34.64,27.21 37.08,24.77 37.08,24.13 39.24,21.97 v39.62,21.97
  Bottom 0.254: 36.58,51.05 J1.3 36.58,42.67 40.64,38.61 40.64,22.86 v39.62,21.97
PWM2/E25  (via drill 0.38)
  Top 0.254: IC1.49 34.74,25.71 v39.88,20.57
  Bottom 0.254: J1.2 39.12,44.07 41.27,41.91 41.27,21.97 v39.88,20.57
PWM3/E23  (via drill 0.38)
  Top 0.254: IC1.50 34.48,25.21 38.86,20.83 38.86,20.32 v39.88,19.3
  Bottom 0.254: v39.88,19.3 40.51,19.3 41.78,20.57 41.78,50.67 J1.1
PWM4/MODE  (via drill 0.38)
  Top 0.254: IC1.100 49.56,12.6 v51.05,14.1 | R1.2 58.86,10.35 MODE.1
  Bottom 0.254: v51.05,14.1 56.13,14.1 58.55,11.68 58.55,10.67 MODE.1
PWM5/E2*  (via drill 0.38)
  Top 0.254: IC1.99 49.06,13.5 51.56,16 51.56,23.37 50.93,24.13 v50.8,24.38
  Bottom 0.254: v50.8,24.38 49.91,25.27 49.91,30.23 54.99,35.31 54.99,44.58 50.8,48.77 JP1.6
PWM6/E7*  (via drill 0.38)
  Top 0.254: IC1.97 48.06,13.52 50.67,16.13 v50.67,22.61
  Bottom 0.254: v50.67,22.61 49.4,24 49.4,30.61 54.36,35.56 54.36,42.93 48.26,49.02 JP1.7
RD1/E19*  (via drill 0.38)
  Top 0.254: IC1.66 35.25,17.21 v35.81,16.26 | v29.84,45.21 49.28,45.21 53.34,49.28 JP1.5
  Bottom 0.254: v35.81,16.26 36.58,16.26 37.21,16.89 37.21,32.13 29.84,39.5 v29.84,45.21
RESET#  (via drill 0.38)
  Top 0.254: IC1.24 42.06,32.62 43.05,31.62 45.09,31.62 v45.47,31.75 | v53.47,36.45 53.47,37.68 RESET.2 | JP4.1 31.62,2.54 30.73,3.43 | 30.73,3.43 30.73,4.92 IC2.1 30.74,6.45 R7.1 | C9.1 30.62,3.31 30.73,3.43 | v44.07,47.5 22.99,47.5 v22.73,47.37
  Bottom 0.254: v45.47,31.75 49.28,31.75 53.47,36.2 v53.47,36.45 50.8,36.45 44.07,43.31 v44.07,47.5 | v22.73,47.37 22.73,46.99 19.3,43.56 8.76,43.56 5.08,39.88 5.08,19.18 1.91,16 1.91,5.33 3.43,3.81 14.22,3.81 17.14,0.89 31.37,0.89 JP4.1
RTS1/E11*  (via drill 0.38)
  Top 0.254: IC1.95 47.06,13.66 49.78,16.38 v49.78,18.29
  Bottom 0.254: v49.78,18.29 51.18,19.68 61.47,19.68 62.1,20.32 64.14,20.32 65.53,21.72 UEXT.5
RTXC1
  Top 0.254: X3.1 51.82,36.42 51.82,36.07 51.44,35.69 49.78,35.69 47.54,37.93 C8.1 47.21,38.61 45.85,38.61 44.7,37.47 43.05,37.47 42.55,36.96 42.55,34.92 42.56,34.94 IC1.23
RTXC2
  Top 0.254: IC1.25 41.56,34.7 42.04,35.18 42.04,37.21 42.8,37.97 44.32,37.97 46.35,40.01 47.38,40.01 C7.1 47.49,40.63 48.26,41.4 50.29,41.4 51.18,40.51 51.18,38.1 50.8,37.72 50.8,36.53 X3.4
RXD0/E20*
  Top 0.254: JP1.1 63.63,50.67 63.63,48.51 61.59,46.48 59.56,44.45 59.56,33.15 57.13,30.71 IC1.142
RXD1/E3*  (via drill 0.38)
  Top 0.254: IC1.106 52.56,18.14 v52.96,18.54
  Bottom 0.254: v52.96,18.54 62.48,18.54 UEXT.4
RXD2/E37*  (via drill 0.38)
  Top 0.254: IC1.26 41.06,32.6 v43.43,30.73 | IC1.92 45.56,10.76 45.21,10.41 v44.7,10.41
  Bottom 0.254: v43.43,30.73 43.43,14.22 44.7,12.95 v44.7,10.41
SCK0/E42*  (via drill 0.38)
  Top 0.254: IC1.89 44.06,21.22 37.72,27.56 v36.32,27.56
  Bottom 0.254: v36.32,27.56 28.96,34.42 J1.6
SCK1/E10*
  Top 0.254: IC1.112 58.13,15.71 59.44,17.02 59.44,24.38 60.45,25.4 64.26,25.4 UEXT.9
SCL0/E31*  (via drill 0.38)
  Top 0.254: IC1.34 37.06,30.5 46.86,20.7 48.77,20.7 v48.9,20.83 | R15.1 63.12,35.81 v60.45,38.48 | v56.13,38.61 v57.91,38.61
  Bottom 0.254: v48.9,20.83 50.93,20.83 53.21,23.11 53.21,30.99 56.13,33.91 v56.13,38.61 56.13,50.55 JP1.4 | v60.45,38.48 57.91,38.48 v57.91,38.61
SD_CLK  (via drill 0.38)
  Top 0.254: X5.CLK 18.02,6.72 19.56,8.26 27.94,8.26 v28.45,8.76 | IC1.85 42.06,10.01 v42.04,10.41
  Bottom 0.254: v28.45,8.76 40.26,8.76 41.91,10.41 v42.04,10.41
SD_CMD  (via drill 0.38)
  Top 0.254: IC1.83 41.06,10.45 40.51,9.91 40.55,7.91 v40.39,7.87 | X5.DI 20.22,4.67 21.21,3.68 24,3.68 v26.67,6.35
  Bottom 0.254: v26.67,6.35 29.72,6.35 31.37,8 40.51,8 v40.39,7.87
SD_DAT0
  Top 0.254: X5.DO 15.82,6.68 18.16,8.89 26.54,8.89 28.07,10.41 39.12,10.41 39.56,10.86 IC1.80
SD_DAT1
  Top 0.254: IC1.75 37.06,11.15 36.83,10.92 27.3,10.92 26.04,9.65 18.03,9.65 14.73,6.35 14.73,5.55 X5.RS2
SD_DAT2  (via drill 0.38)
  Top 0.254: IC1.73 36.06,11.93 35.69,11.56 35.18,11.56 v35.05,11.81 | v23.88,5.46 22.5,5.46 X5.RS1
  Bottom 0.254: v35.05,11.81 35.05,11.56 33.15,9.65 28.07,9.65 v23.88,5.46
SD_DAT3  (via drill 0.38)
  Top 0.254: X5.CS 21.32,6.21 21.72,6.99 23.5,6.99 v23.75,6.73 | IC1.71 34.56,14.71 34.92,14.35 34.92,13.59 v33.53,12.19
  Bottom 0.254: v23.75,6.73 23.88,6.48 29.46,12.06 33.4,12.06 v33.53,12.19
SD_PWR
  Top 0.254: X5.VCC 19.05,5.41 | T2.3 37.2,8.43 C10.1
  Top 0.305: T2.3 29.39,8.43 28.7,7.75 20.19,7.75 19.05,6.6 19.05,5.41
  Top 0.406: 37.2,8.43 37.25,8.43 R14.2
SDA0/E33*  (via drill 0.38)
  Top 0.254: IC1.35 36.56,29.86 47.12,19.3 v48.77,19.3 | R16.1 60.96,36.83 v60.45,37.34
  Bottom 0.254: JP1.3 58.29,50.67 58.29,50.42 58.42,50.55 JP1.3 | JP1.3 58.55,50.93 | v48.77,19.3 48.77,19.43 49.66,20.32 51.18,20.32 56.26,25.4 56.26,33.02 57.02,33.78 57.02,37.85 | 57.02,37.85 57.02,48.13 58.42,49.53 JP1.3 | v60.45,37.34 57.02,37.34 57.02,37.85
SSEL1/E12*
  Top 0.254: IC1.113 57.61,16.21 58.93,17.53 58.93,25.15 60.45,26.67 UEXT.10
TD1/E15*  (via drill 0.38)
  Top 0.254: IC1.67 33.09,16.71 32.26,15.88 v32.26,14.22 | v30.73,46.23 44.96,46.23 45.97,47.24 45.97,49.28 45.72,49.53 JP1.8
  Bottom 0.254: v32.26,14.22 37.34,14.22 38.1,14.99 38.1,23.11 37.72,23.5 37.72,32.38 30.73,39.37 v30.73,46.23
TXD0/E18*
  Top 0.254: IC1.141 55.01,30.21 54.61,30.61 54.61,31.75 55.63,32.77 57.53,32.77 59.05,34.29 59.05,47.75 61.09,49.78 61.09,50.67 JP1.2
TXD1/E5*  (via drill 0.38)
  Top 0.254: IC1.107 53.06,16.74 v53.98,17.65
  Bottom 0.254: v53.98,17.65 64.39,17.65 65.66,18.92 UEXT.3
USB_CON2  (via drill 0.38)
  Top 0.254: IC1.48 32.84,26.21 v32.13,26.92 | v20.19,39.75 17.79,39.75 R6.1
  Bottom 0.254: v32.13,26.92 32.13,27.81 v20.19,39.75
USB_PWR_RD
  Top 0.254: IC1.51 33.07,24.71 30.2,27.58 17.6,27.58 F1.2
  Top 0.61: F1.2 12.68,27.96 10.41,30.23 10.41,35.31 11.43,36.32 13.1,36.32 X1.1
VBAT  (via drill 0.38)
  Top 0.254: 40.56,36.07 IC1.27 | 40.56,36.07 D1.C | 40.56,36.07 40.56,31.83 42.8,29.59 43.69,29.59 v44.58,30.48 | v43.43,49.02 42.67,48.26 21.88,48.26 R13.1
  Bottom 0.254: v44.58,30.48 44.58,32.13 47.75,35.31 47.75,38.61 43.18,43.18 43.18,48.77 v43.43,49.02
VBUS
  Top 0.254: IC1.40 34.66,30.21 35.43,30.99 35.43,32.51 34.29,33.66 31.5,33.66 27.81,37.34 27.81,44.07 26.29,45.59 21.21,45.59 18.41,48.39 13.37,48.39 R11.1
VCC  (via drill 0.38, 0.61)
  Top 0.254: IC1.14 47.06,34.61 47.75,35.31 48.42,35.56 | 48.42,35.56 C1.1 | 45.06,35.05 IC1.18 | 45.06,35.08 45.06,35.05 | IC1.17 45.56,34.55 45.06,35.05 | R7.2 28.97,7 | 32.85,7.75 T2.2 | 28.97,5.06 IC2.2 28.96,5.05 28.96,5.71 | IC1.121 57.04,20.21 57.38,20.65 | 57.4,20.7 57.38,20.65 | 57.4,20.7 57.4,27.43 57.53,27.34 C3.1 56.62,28.71 IC1.138 | 46.1,36.83 44.48,36.83 | 48.42,35.56 48.39,35.56 48.26,35.69 | IC1.41 28.84,29.71 v28.32,30.23 28.57,30.1 29.46,30.99 29.46,31.54 R12.2 | C2.1 32.36,19.21 IC1.62 37.05,19.21 | C2.1 31.58,20.21 | 30.02,19.81 29.93,20.11 v29.46,20.19 | C2.1 31.37,19.81 | 27.53,20.57 IC4.4 IC4.2 | D1.A 43.89,36.15 44.58,36.83 | 49.91,4.7 49.91,5.21 | v60.71,28.96 60.71,29.08 | IC1.6 51.06,34.92 50.93,35.05 | IC1.102 50.56,11.19 49.78,10.41 49.78,10.07 C4.1 49.54,9.78 49.91,9.78 | IC1.77 38.06,16.22 38.61,16.76 38.99,17.27 v39.12,17.14 | 35.8,20.21 IC1.60 | 35.8,20.21 35.81,20.19 31.81,20.19 C2.1 | 35.8,20.21 36.18,20.21 37.08,19.3 | IC1.114 56.84,16.71 57.4,17.27 57.4,20.7 | 57.4,20.7 57.4,20.75 57.38,20.65 | R15.2 R16.2 61.21,32.68 v60.83,31.75
  Top 0.406: 45.06,35.08 D1.A 44.48,36.83 | C3.1 59.2,27.57 60.71,29.08 | 46.1,36.83 47.12,36.83 48.26,35.69 48.9,35.05 50.93,35.05 57.4,35.05 v57.91,34.54 | 46.1,36.83 44.58,36.83 | v46.1,37.72 46.1,36.83
  Top 0.61: 28.97,7 29.72,7.75 32.85,7.75 | 35.56,4.7 35.43,4.91 T2.2 | 35.56,4.7 JP4.2 | 28.97,5.06 R7.2 | 28.96,5.71 27.81,5.71 v25.65,3.94 | 35.56,4.7 49.91,4.7 58.8,4.7 64.39,10.29 66.29,10.29 67.18,11.18 67.18,14.86 UEXT.1 | 49.91,5.21 49.91,9.78 | v19.05,41.53 18.06,41.53 T1.2
  Top 0.813: 31.37,19.81 30.02,19.81 | v39.12,17.14 37.05,19.21
  Bottom 0.254: v28.32,30.23 28.07,30.1 | 60.71,31.75 61.09,31.62 v60.83,31.75
  Bottom 0.406: v57.91,34.54 60.71,31.75 v60.71,28.96
  Bottom 0.61: v46.1,37.72 45.97,37.08 42.42,33.53 42.42,18.54 41.02,17.14 v39.12,17.14
  Bottom 0.813: v25.15,22.99 25.15,26.67 v28.32,30.23 | 28.07,30.1 19.05,39.12 v19.05,41.53 | v25.65,3.94 25.53,4.06 23.62,4.06 22.1,5.59 22.1,10.67 23.88,12.45 v23.88,13.34
  other vias: 25.15,21.59 25.15,20.19 25.15,18.8 25.15,17.4 26.67,17.4 29.46,17.4 29.46,18.8 29.46,21.59 27.94,17.4 29.46,22.99
  pour Top: 22.61,25.65 22.61,12.7 29.97,12.7 29.97,25.65
VIN
  Top 0.254: 11.33,13.43 D3.A
  Top 0.813: X6.IN 11.33,13.43
  Bottom 0.813: JP4.6 45.72,4.95 44.83,5.84 31.5,5.84 28.07,2.67 22.99,2.67 18.67,6.73 18.67,11.68 16.64,13.72 13.11,13.72 11.33,11.94 X6.IN
XTAL1
  Top 0.254: IC1.31 38.56,37.54 40.89,39.88 40.92,39.88 X2.1 42.2,40.84 C6.1
XTAL2
  Top 0.254: IC1.33 37.56,36.41 33.02,40.19 | 33.02,40.19 X2.2 | C5.1 33.77,39.44 33.02,40.19
(copper drawn outside any net)
  shapes: Bottom circle x2

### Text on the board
tPlace: 13 | 12 | 11 | 10 | 9 8 7 6 5 4 3 2 1 0 | VBAT | GND | PWM | #1 | PWM | #2 | PWM | #3 | TD | PWM | #6 | PWM | #5 | RD | SCL | SDA | OUT | IN | SPI1 | SCK | SPI1 | MISO | SPI1 | MOSI | CAN1 | CAN1 | *OD* | *OD* | COM1 | COM1 | FEZ Domino | V1.1 | + | 10 | 4 6 8 | 3 5 7 9 | + | - | GND | VCC | + | 14 15 16 17 18 | 19 | RST | 3V3 | 5V | GND | Vin | A0 | A1 | A2 | A3 | A4 | A5 | 7 to 12V | MicroSD
bPlace: FEZ | (Freakin' Easy!) | SPI2 | DIO | 10 | SCK | Based on USBizi Chipset | SPI2 | SPI2 | MOSI | MISO | www.TinyCLR.com | COM2 CTS | COM2 RTS | COM2 IN | 4 6 8 | 3 5 7 9 | COM2 OUT | GND | 3.3V | Embedded Development using | Microsoft's .NET Micro Framework | HYT09
Reference: C8 | R7 | R5 | R6 | R4 | C3 | C2 | R9 | R8 | R1 | R2 | C1 | C4 | C5 | X2 | C7 | C6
